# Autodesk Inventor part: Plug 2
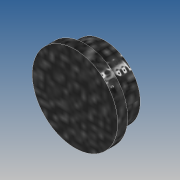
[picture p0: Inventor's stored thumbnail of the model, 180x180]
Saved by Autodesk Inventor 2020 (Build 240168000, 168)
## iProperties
Created: 2019-10
Part Number: Plug 2
Material: Generic
Document SubType Name: Modeling
Designer: yello
Density: 1 g/cm^3
Appearance: Default
Author: yello
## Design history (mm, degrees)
sketch "Sketch1"
  geometry: C1 r 4.25 at (0, 0); 1 further point
  constraints: 1 centre point, 1 coincident
  dimensions: "d0" = 8.5 diameter of C1
extrude "Extrusion1" new body sketch "Sketch1" distance "d1" = 1; taper "d2" = 0 deg
sketch "Sketch2"
  geometry: C1 r 3.5 at (0, 0); 1 further point
  constraints: 1 centre point, 1 coincident
  dimensions: "d3" = 7 diameter of C1
extrude "Extrusion2" join sketch "Sketch2" distance "d4" = 2; taper "d5" = 0 deg
body "Solid1"
